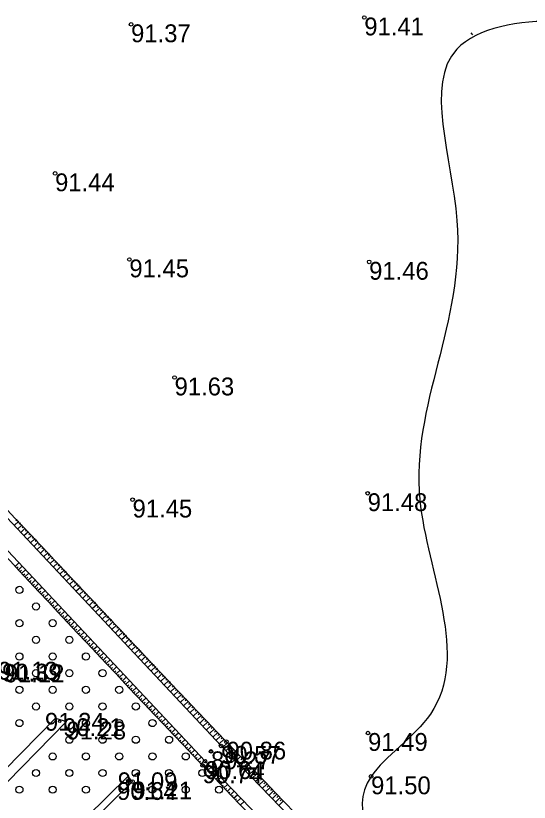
# Model space of a CAD drawing. Extents: x 316000 to 728450, y 314368 to 726000.
# Drawn here: x 725766.2 to 725874.3, y 315550.4 to 315715.7 of the extents above; entities that cross this region are included whole.
import ezdxf

# ---------------------------------------------------------------- set-up
doc = ezdxf.new("R2010")
doc.units = 0
for name, color, linetype in [('HIDG_ELEM_####_####_#', 7, 'Continuous'), ('HIDG_GRAV_####_####_#', 7, 'Continuous'), ('RELJ_AATZ_####_TKST_#', 7, 'Continuous'), ('RELJ_ELEM_####_####_#', 7, 'Continuous'), ('RELJ_HORZ_PAMT_####_#', 7, 'Continuous'), ('RELJ_NOGA_####_####_#', 7, 'Continuous'), ('TERT_ELEM_####_####_#', 7, 'Continuous')]:
    doc.layers.add(name, color=color, linetype=linetype)

msp = doc.modelspace()

# ---------------------------------------------------------------- linework, layer by layer
at = {"layer": 'HIDG_ELEM_####_####_#'}
for centre in [(725775.48, 315567.37), (725807.32, 315561.05), (725789.94, 315554.83)]:
    msp.add_circle(centre, 0.225, dxfattribs=at)
at = {"layer": 'HIDG_GRAV_####_####_#'}
for points in [[(726259.18, 315086.52), (726260.77, 315088.86), (726179.01, 315175.77), (726127.86, 315229.06), (726063.06, 315296.07), (725998.34, 315364.32), (725936.65, 315430.32), (725875.35, 315494.08), (725809.44, 315562.19), (725743.94, 315631.87)], [(725741.16, 315628.11), (725806.06, 315558.99), (725870.9, 315491.87), (725934.12, 315427.08), (725995.78, 315361.63), (726059.85, 315293.4), (726126.03, 315226.73), (726194.49, 315154.86), (726259.18, 315086.52)], [(725774.6, 315568.07), (725776.9, 315567.31), (725667.35, 315455.53), (725666.51, 315458.03), (725774.6, 315568.07)], [(725789.82, 315555.77), (725790.78, 315554.71), (725668.4, 315434.39), (725667.72, 315435.8), (725789.82, 315555.77)]]:
    msp.add_lwpolyline(points, dxfattribs=at)
at = {"layer": 'RELJ_ELEM_####_####_#'}
for centre in [(725839.57, 315715.32), (725790.5, 315713.88), (725774.51, 315682.55), (725790.14, 315664.46), (725840.59, 315663.95), (725799.65, 315639.64), (725790.81, 315613.97), (725840.28, 315615.31), (725840.36, 315564.91), (725810.58, 315563.08), (725807.32, 315561.05), (725809.44, 315562.19), (725805.54, 315558.12), (725806.06, 315558.99), (725789.94, 315554.83), (725790.78, 315554.71), (725841, 315555.79)]:
    msp.add_circle(centre, 0.375, dxfattribs=at)
at = {"layer": 'RELJ_HORZ_PAMT_####_#'}
msp.add_line((725862.02, 315712.08), (725862.31, 315711.67), dxfattribs=at)
msp.add_spline([(726116.34, 315699.09), (726105.94, 315702.69), (726040.13, 315715), (725990.82, 315710.42), (725942.03, 315708.25), (725920.28, 315706.77), (725880.37, 315714.51), (725859.05, 315708.68), (725859.05, 315672.66), (725851.26, 315613.97), (725853.47, 315568.9), (725841, 315555.79), (725885.56, 315509.63), (725935.94, 315461.49), (725983.42, 315406.25), (726032.86, 315360.51), (726082.85, 315311.19), (726122.23, 315248.76), (726137.05, 315229.29), (726180.19, 315183.1), (726194.52, 315168.27), (726211.91, 315146.93), (726212.51, 315143.16)], degree=3, dxfattribs=at)
at = {"layer": 'RELJ_NOGA_####_####_#'}
for p, q in [((725766.86, 315609.42), (725765.9, 315608.51)), ((725766.52, 315609.79), (725766.23, 315609.51)), ((725767.55, 315608.69), (725766.58, 315607.78)), ((725767.2, 315609.06), (725766.92, 315608.79)), ((725768.23, 315607.97), (725767.27, 315607.06)), ((725767.89, 315608.33), (725767.6, 315608.06)), ((725768.58, 315607.6), (725768.29, 315607.33)), ((725768.92, 315607.24), (725767.95, 315606.33)), ((725769.61, 315606.51), (725768.64, 315605.6)), ((725769.26, 315606.88), (725768.97, 315606.6)), ((725769.95, 315606.15), (725769.66, 315605.87)), ((725770.29, 315605.78), (725769.32, 315604.87)), ((725770.98, 315605.06), (725770.01, 315604.14)), ((725770.64, 315605.42), (725770.34, 315605.15)), ((725771.67, 315604.33), (725770.69, 315603.41)), ((725771.32, 315604.69), (725771.03, 315604.42)), ((725772.35, 315603.6), (725771.38, 315602.68)), ((725772.01, 315603.97), (725771.72, 315603.69)), ((725773.04, 315602.87), (725772.06, 315601.96)), ((725772.69, 315603.24), (725772.4, 315602.96)), ((725773.72, 315602.15), (725772.75, 315601.23)), ((725773.38, 315602.51), (725773.09, 315602.24)), ((725774.41, 315601.42), (725773.43, 315600.5)), ((725774.07, 315601.78), (725773.77, 315601.51)), ((725774.75, 315601.06), (725774.46, 315600.78)), ((725766.19, 315600.01), (725766.91, 315600.69)), ((725766.53, 315599.65), (725766.75, 315599.85)), ((725766.88, 315599.29), (725767.59, 315599.96)), ((725775.1, 315600.69), (725774.12, 315599.77)), ((725775.78, 315599.97), (725774.8, 315599.04)), ((725775.44, 315600.33), (725775.15, 315600.05)), ((725776.13, 315599.6), (725775.83, 315599.32)), ((725767.22, 315598.92), (725767.43, 315599.12)), ((725767.56, 315598.56), (725768.28, 315599.23)), ((725767.9, 315598.19), (725768.12, 315598.39)), ((725768.25, 315597.83), (725768.96, 315598.5)), ((725768.59, 315597.46), (725768.8, 315597.67)), ((725768.93, 315597.1), (725769.65, 315597.77)), ((725776.47, 315599.24), (725775.49, 315598.31)), ((725777.15, 315598.51), (725776.17, 315597.58)), ((725776.81, 315598.87), (725776.52, 315598.6)), ((725777.84, 315597.78), (725776.86, 315596.85)), ((725777.5, 315598.15), (725777.2, 315597.87)), ((725769.27, 315596.73), (725769.49, 315596.94)), ((725769.62, 315596.37), (725770.33, 315597.04)), ((725769.96, 315596.01), (725770.17, 315596.21)), ((725770.3, 315595.64), (725771.02, 315596.31)), ((725778.53, 315597.06), (725777.54, 315596.13)), ((725778.18, 315597.42), (725777.89, 315597.14)), ((725779.21, 315596.33), (725778.23, 315595.4)), ((725778.87, 315596.69), (725778.57, 315596.41)), ((725779.56, 315595.96), (725779.26, 315595.69)), ((725770.64, 315595.28), (725770.86, 315595.48)), ((725770.98, 315594.91), (725771.7, 315595.59)), ((725771.33, 315594.55), (725771.54, 315594.75)), ((725771.67, 315594.18), (725772.39, 315594.86)), ((725779.9, 315595.6), (725778.91, 315594.67)), ((725780.59, 315594.87), (725779.6, 315593.94)), ((725780.24, 315595.24), (725779.95, 315594.96)), ((725780.93, 315594.51), (725780.63, 315594.23)), ((725772.01, 315593.82), (725772.23, 315594.02)), ((725772.35, 315593.45), (725773.07, 315594.13)), ((725772.7, 315593.09), (725772.91, 315593.29)), ((725773.04, 315592.73), (725773.76, 315593.4)), ((725773.72, 315592), (725774.44, 315592.67)), ((725781.27, 315594.15), (725780.28, 315593.21)), ((725781.96, 315593.42), (725780.97, 315592.48)), ((725781.62, 315593.78), (725781.32, 315593.5)), ((725782.64, 315592.69), (725781.65, 315591.75)), ((725782.3, 315593.06), (725782, 315592.77)), ((725773.38, 315592.36), (725773.6, 315592.56)), ((725774.07, 315591.63), (725774.28, 315591.83)), ((725774.41, 315591.27), (725775.12, 315591.94)), ((725774.75, 315590.9), (725774.96, 315591.1)), ((725775.09, 315590.54), (725775.81, 315591.21)), ((725783.33, 315591.96), (725782.34, 315591.03)), ((725782.99, 315592.33), (725782.69, 315592.05)), ((725784.02, 315591.24), (725783.02, 315590.3)), ((725783.67, 315591.6), (725783.38, 315591.32)), ((725775.43, 315590.17), (725775.65, 315590.38)), ((725775.78, 315589.81), (725776.49, 315590.48)), ((725776.12, 315589.45), (725776.33, 315589.65)), ((725776.46, 315589.08), (725777.18, 315589.75)), ((725784.7, 315590.51), (725783.71, 315589.57)), ((725784.36, 315590.87), (725784.06, 315590.59)), ((725785.39, 315589.78), (725784.39, 315588.84)), ((725785.05, 315590.15), (725784.75, 315589.86)), ((725785.73, 315589.42), (725785.43, 315589.14)), ((725776.8, 315588.72), (725777.02, 315588.92)), ((725777.15, 315588.35), (725777.86, 315589.02)), ((725777.49, 315587.99), (725777.7, 315588.19)), ((725777.83, 315587.62), (725778.55, 315588.3)), ((725786.08, 315589.05), (725785.08, 315588.11)), ((725786.76, 315588.33), (725785.76, 315587.38)), ((725786.42, 315588.69), (725786.12, 315588.41)), ((725787.11, 315587.96), (725786.8, 315587.68)), ((725778.17, 315587.26), (725778.39, 315587.46)), ((725778.52, 315586.89), (725779.23, 315587.57)), ((725778.86, 315586.53), (725779.07, 315586.73)), ((725779.2, 315586.16), (725779.92, 315586.84)), ((725779.88, 315585.44), (725780.6, 315586.11)), ((725787.45, 315587.6), (725786.45, 315586.65)), ((725788.13, 315586.87), (725787.13, 315585.92)), ((725787.79, 315587.24), (725787.49, 315586.95)), ((725788.82, 315586.15), (725787.81, 315585.2)), ((725788.48, 315586.51), (725788.18, 315586.22)), ((725779.54, 315585.8), (725779.76, 315586)), ((725780.23, 315585.07), (725780.44, 315585.27)), ((725780.57, 315584.71), (725781.28, 315585.38)), ((725780.91, 315584.34), (725781.13, 315584.54)), ((725781.25, 315583.98), (725781.97, 315584.65)), ((725789.51, 315585.42), (725788.5, 315584.47)), ((725789.16, 315585.78), (725788.86, 315585.5)), ((725790.19, 315584.69), (725789.18, 315583.74)), ((725789.85, 315585.05), (725789.55, 315584.77)), ((725781.6, 315583.61), (725781.81, 315583.82)), ((725781.94, 315583.25), (725782.65, 315583.92)), ((725782.28, 315582.88), (725782.5, 315583.09)), ((725782.62, 315582.52), (725783.34, 315583.19)), ((725790.88, 315583.96), (725789.87, 315583.01)), ((725790.54, 315584.33), (725790.23, 315584.04)), ((725791.57, 315583.24), (725790.55, 315582.28)), ((725791.22, 315583.6), (725790.92, 315583.31)), ((725791.91, 315582.87), (725791.61, 315582.59)), ((725782.97, 315582.16), (725783.18, 315582.36)), ((725783.31, 315581.79), (725784.02, 315582.46)), ((725783.65, 315581.43), (725783.86, 315581.63)), ((725783.99, 315581.06), (725784.71, 315581.73)), ((725792.25, 315582.51), (725791.24, 315581.55)), ((725792.94, 315581.78), (725791.92, 315580.82)), ((725792.6, 315582.14), (725792.29, 315581.86)), ((725793.28, 315581.42), (725792.98, 315581.13)), ((725784.33, 315580.7), (725784.55, 315580.9)), ((725784.68, 315580.33), (725785.39, 315581.01)), ((725785.02, 315579.97), (725785.23, 315580.17)), ((725785.36, 315579.6), (725786.08, 315580.28)), ((725785.7, 315579.24), (725785.92, 315579.44)), ((725786.05, 315578.88), (725786.76, 315579.55)), ((725793.62, 315581.05), (725792.61, 315580.1)), ((725794.31, 315580.33), (725793.29, 315579.37)), ((725793.97, 315580.69), (725793.66, 315580.4)), ((725795, 315579.6), (725793.98, 315578.64)), ((725794.65, 315579.96), (725794.35, 315579.67)), ((725786.39, 315578.51), (725786.6, 315578.71)), ((725786.73, 315578.15), (725787.45, 315578.82)), ((725787.07, 315577.78), (725787.29, 315577.98)), ((725787.42, 315577.42), (725788.13, 315578.09)), ((725795.68, 315578.87), (725794.66, 315577.91)), ((725795.34, 315579.23), (725795.03, 315578.95)), ((725796.37, 315578.14), (725795.35, 315577.18)), ((725796.03, 315578.51), (725795.72, 315578.22)), ((725796.71, 315577.78), (725796.41, 315577.49)), ((725787.76, 315577.05), (725787.97, 315577.25)), ((725788.1, 315576.69), (725788.81, 315577.36)), ((725788.44, 315576.32), (725788.66, 315576.53)), ((725788.78, 315575.96), (725789.5, 315576.63)), ((725797.06, 315577.42), (725796.03, 315576.45)), ((725797.74, 315576.69), (725796.72, 315575.72)), ((725797.4, 315577.05), (725797.09, 315576.76)), ((725798.08, 315576.33), (725797.78, 315576.04)), ((725789.13, 315575.6), (725789.34, 315575.8)), ((725789.47, 315575.23), (725790.18, 315575.9)), ((725789.81, 315574.87), (725790.03, 315575.07)), ((725790.15, 315574.5), (725790.87, 315575.17)), ((725798.43, 315575.96), (725797.4, 315574.99)), ((725799.11, 315575.23), (725798.09, 315574.27)), ((725798.77, 315575.6), (725798.46, 315575.31)), ((725799.8, 315574.51), (725798.77, 315573.54)), ((725799.46, 315574.87), (725799.15, 315574.58)), ((725790.5, 315574.14), (725790.71, 315574.34)), ((725790.84, 315573.77), (725791.55, 315574.44)), ((725791.18, 315573.41), (725791.39, 315573.61)), ((725791.52, 315573.04), (725792.24, 315573.72)), ((725791.87, 315572.68), (725792.08, 315572.88)), ((725792.21, 315572.32), (725792.92, 315572.99)), ((725800.49, 315573.78), (725799.46, 315572.81)), ((725800.14, 315574.14), (725799.84, 315573.85)), ((725801.17, 315573.05), (725800.14, 315572.08)), ((725800.83, 315573.42), (725800.52, 315573.12)), ((725792.55, 315571.95), (725792.76, 315572.15)), ((725792.89, 315571.59), (725793.61, 315572.26)), ((725793.23, 315571.22), (725793.45, 315571.42)), ((725793.58, 315570.86), (725794.29, 315571.53)), ((725801.86, 315572.32), (725800.83, 315571.35)), ((725801.52, 315572.69), (725801.21, 315572.4)), ((725802.55, 315571.6), (725801.51, 315570.62)), ((725802.2, 315571.96), (725801.89, 315571.67)), ((725802.89, 315571.23), (725802.58, 315570.94)), ((725793.92, 315570.49), (725794.13, 315570.69)), ((725794.26, 315570.13), (725794.98, 315570.8)), ((725794.6, 315569.76), (725794.82, 315569.97)), ((725794.95, 315569.4), (725795.66, 315570.07)), ((725803.23, 315570.87), (725802.2, 315569.89)), ((725803.92, 315570.14), (725802.88, 315569.17)), ((725803.57, 315570.51), (725803.26, 315570.21)), ((725804.26, 315569.78), (725803.95, 315569.49)), ((725795.29, 315569.04), (725795.5, 315569.24)), ((725795.63, 315568.67), (725796.34, 315569.34)), ((725795.97, 315568.31), (725796.19, 315568.51)), ((725796.32, 315567.94), (725797.03, 315568.61)), ((725797, 315567.21), (725797.71, 315567.88)), ((725804.6, 315569.42), (725803.57, 315568.44)), ((725805.29, 315568.69), (725804.25, 315567.71)), ((725804.95, 315569.05), (725804.64, 315568.76)), ((725805.98, 315567.96), (725804.94, 315566.98)), ((725805.63, 315568.32), (725805.32, 315568.03)), ((725796.66, 315567.58), (725796.87, 315567.78)), ((725797.34, 315566.85), (725797.56, 315567.05)), ((725797.68, 315566.48), (725798.4, 315567.15)), ((725798.03, 315566.12), (725798.24, 315566.32)), ((725798.37, 315565.76), (725799.08, 315566.43)), ((725806.66, 315567.23), (725805.62, 315566.25)), ((725806.32, 315567.6), (725806.01, 315567.3)), ((725807.35, 315566.51), (725806.31, 315565.52)), ((725807.01, 315566.87), (725806.69, 315566.57)), ((725798.71, 315565.39), (725798.93, 315565.59)), ((725799.05, 315565.03), (725799.77, 315565.7)), ((725799.4, 315564.66), (725799.61, 315564.86)), ((725799.74, 315564.3), (725800.45, 315564.97)), ((725808.04, 315565.78), (725806.99, 315564.79)), ((725807.69, 315566.14), (725807.38, 315565.85)), ((725808.72, 315565.05), (725807.68, 315564.06)), ((725808.38, 315565.41), (725808.06, 315565.12)), ((725809.06, 315564.69), (725808.75, 315564.39)), ((725800.08, 315563.93), (725800.29, 315564.13)), ((725800.42, 315563.57), (725801.14, 315564.24)), ((725800.77, 315563.2), (725800.98, 315563.41)), ((725801.11, 315562.84), (725801.82, 315563.51)), ((725809.41, 315564.32), (725808.36, 315563.34)), ((725810.09, 315563.6), (725809.05, 315562.61)), ((725809.75, 315563.96), (725809.44, 315563.66)), ((725810.44, 315563.23), (725810.12, 315562.94)), ((725801.45, 315562.48), (725801.66, 315562.68)), ((725801.79, 315562.11), (725802.51, 315562.78)), ((725802.13, 315561.75), (725802.35, 315561.95)), ((725802.48, 315561.38), (725803.19, 315562.05)), ((725803.16, 315560.65), (725803.87, 315561.32)), ((725810.78, 315562.87), (725809.74, 315561.88)), ((725811.47, 315562.14), (725810.43, 315561.16)), ((725811.12, 315562.51), (725810.81, 315562.21)), ((725812.15, 315561.42), (725811.13, 315560.44)), ((725811.81, 315561.78), (725811.5, 315561.49)), ((725802.82, 315561.02), (725803.03, 315561.22)), ((725803.5, 315560.29), (725803.72, 315560.49)), ((725803.85, 315559.92), (725804.56, 315560.59)), ((725804.19, 315559.56), (725804.4, 315559.76)), ((725804.53, 315559.2), (725805.24, 315559.86)), ((725812.84, 315560.69), (725811.82, 315559.72)), ((725812.5, 315561.05), (725812.19, 315560.76)), ((725813.53, 315559.96), (725812.52, 315559.01)), ((725813.19, 315560.33), (725812.88, 315560.04)), ((725813.87, 315559.6), (725813.57, 315559.31)), ((725804.87, 315558.83), (725805.09, 315559.03)), ((725805.22, 315558.47), (725805.93, 315559.14)), ((725805.56, 315558.1), (725805.77, 315558.3)), ((725805.9, 315557.74), (725806.62, 315558.41)), ((725814.22, 315559.24), (725813.22, 315558.29)), ((725814.91, 315558.51), (725813.91, 315557.57)), ((725814.56, 315558.87), (725814.26, 315558.59)), ((725815.25, 315558.15), (725814.95, 315557.87)), ((725806.24, 315557.37), (725806.46, 315557.58)), ((725806.58, 315557.01), (725807.31, 315557.7)), ((725806.93, 315556.64), (725807.15, 315556.85)), ((725807.27, 315556.28), (725808.01, 315556.98)), ((725815.6, 315557.79), (725814.61, 315556.85)), ((725816.28, 315557.06), (725815.3, 315556.13)), ((725815.94, 315557.43), (725815.64, 315557.14)), ((725816.97, 315556.34), (725816, 315555.41)), ((725816.63, 315556.7), (725816.34, 315556.42)), ((725807.61, 315555.92), (725807.84, 315556.13)), ((725807.96, 315555.55), (725808.7, 315556.26)), ((725808.3, 315555.19), (725808.52, 315555.4)), ((725808.64, 315554.83), (725809.4, 315555.54)), ((725808.99, 315554.46), (725809.21, 315554.68)), ((725809.33, 315554.1), (725810.09, 315554.82)), ((725817.66, 315555.62), (725816.7, 315554.69)), ((725817.32, 315555.98), (725817.03, 315555.7)), ((725818.36, 315554.89), (725817.39, 315553.97)), ((725818.01, 315555.25), (725817.72, 315554.98)), ((725809.67, 315553.74), (725809.9, 315553.95)), ((725810.02, 315553.37), (725810.79, 315554.1)), ((725810.36, 315553.01), (725810.59, 315553.23)), ((725810.7, 315552.65), (725811.48, 315553.38)), ((725819.05, 315554.17), (725818.09, 315553.25)), ((725818.7, 315554.53), (725818.41, 315554.26)), ((725819.74, 315553.45), (725818.78, 315552.53)), ((725819.39, 315553.81), (725819.1, 315553.53)), ((725820.08, 315553.09), (725819.8, 315552.81)), ((725811.05, 315552.28), (725811.28, 315552.51)), ((725811.39, 315551.92), (725812.18, 315552.66)), ((725811.74, 315551.56), (725811.97, 315551.78)), ((725812.08, 315551.2), (725812.87, 315551.94)), ((725820.43, 315552.72), (725819.48, 315551.81)), ((725821.12, 315552), (725820.17, 315551.1)), ((725820.78, 315552.36), (725820.49, 315552.09)), ((725821.47, 315551.64), (725821.18, 315551.37)), ((725812.43, 315550.83), (725812.66, 315551.06)), ((725812.77, 315550.47), (725813.56, 315551.23)), ((725813.46, 315549.75), (725814.26, 315550.51)), ((725821.81, 315551.28), (725820.87, 315550.38)), ((725822.51, 315550.56), (725821.57, 315549.66)), ((725822.16, 315550.92), (725821.88, 315550.65))]:
    msp.add_line(p, q, dxfattribs=at)
for points in [[(726259.12, 315084.51), (726262.72, 315089.26), (726261.56, 315090.84), (726260.2, 315092.42), (726257.29, 315095.53), (726218.91, 315136.38), (726180.31, 315176.84), (726128.67, 315229.97), (726063.7, 315298.11), (725999.9, 315366.09), (725937.21, 315432.09), (725876.35, 315495.23), (725810.58, 315563.08), (725744.7, 315632.91)], [(725740.86, 315626.98), (725805.54, 315558.12), (725870.39, 315491.15), (725932.8, 315426.8), (725994.98, 315360.84), (726059.66, 315292.12), (726075.75, 315275.46), (726092.08, 315259.04), (726108.47, 315242.67), (726124.69, 315226.14), (726193.27, 315154.03), (726250.06, 315092.6), (726256.32, 315085.83), (726258.82, 315084.29), (726259.12, 315084.51)]]:
    msp.add_spline(points, degree=3, dxfattribs=at)
at = {"layer": 'TERT_ELEM_####_####_#'}
for centre in [(725767, 315595), (725770.5, 315591.5), (725767, 315588), (725774, 315588), (725770.5, 315584.5), (725777.5, 315584.5), (725767, 315581), (725774, 315581), (725781, 315581), (725770.5, 315577.5), (725777.5, 315577.5), (725784.5, 315577.5), (725767, 315574), (725774, 315574), (725781, 315574), (725788, 315574), (725770.5, 315570.5), (725777.5, 315570.5), (725784.5, 315570.5), (725791.5, 315570.5), (725767, 315567), (725781, 315567), (725788, 315567), (725795, 315567), (725777.5, 315563.5), (725784.5, 315563.5), (725791.5, 315563.5), (725798.5, 315563.5), (725774, 315560), (725781, 315560), (725788, 315560), (725795, 315560), (725802, 315560), (725770.5, 315556.5), (725777.5, 315556.5), (725784.5, 315556.5), (725791.5, 315556.5), (725798.5, 315556.5), (725805.5, 315556.5), (725767, 315553), (725774, 315553), (725781, 315553), (725795, 315553), (725802, 315553), (725809, 315553)]:
    msp.add_circle(centre, 0.75, dxfattribs=at)

# ---------------------------------------------------------------- texts
at = {"layer": 'RELJ_AATZ_####_TKST_#'}
for s, p in [('91.41', (725839.57, 315711.57)), ('91.37', (725790.5, 315710.13)), ('91.44', (725774.51, 315678.8)), ('91.45', (725790.14, 315660.71)), ('91.46', (725840.59, 315660.2)), ('91.63', (725799.65, 315635.89)), ('91.48', (725840.28, 315611.56)), ('91.45', (725790.81, 315610.22)), ('91.13', (725762.52, 315576.13)), ('90.39', (725763.35, 315575.73)), ('91.12', (725763.92, 315575.56)), ('91.24', (725772.38, 315565.4)), ('90.21', (725776.2, 315564.26)), ('91.28', (725776.9, 315563.56)), ('91.49', (725840.36, 315561.16)), ('90.86', (725810.58, 315559.33)), ('90.57', (725809.44, 315558.44)), ('89.27', (725807.32, 315557.3)), ('90.74', (725805.54, 315554.37)), ('90.64', (725806.06, 315555.24)), ('91.09', (725787.7, 315552.89)), ('90.64', (725787.56, 315550.85)), ('91.21', (725790.78, 315550.96)), ('91.50', (725841, 315552.04))]:
    msp.add_text(s, height=3.75, dxfattribs=at).set_placement(p)

doc.saveas('drawing.dxf')
